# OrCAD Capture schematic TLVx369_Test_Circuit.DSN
size A; title: TLVx369 Cost-Optimized, 800-nA, 1.8-V, Rail-to-Rail I/O; rev: 1.1; note: Datasheet: SBOS757 EVM: N/A
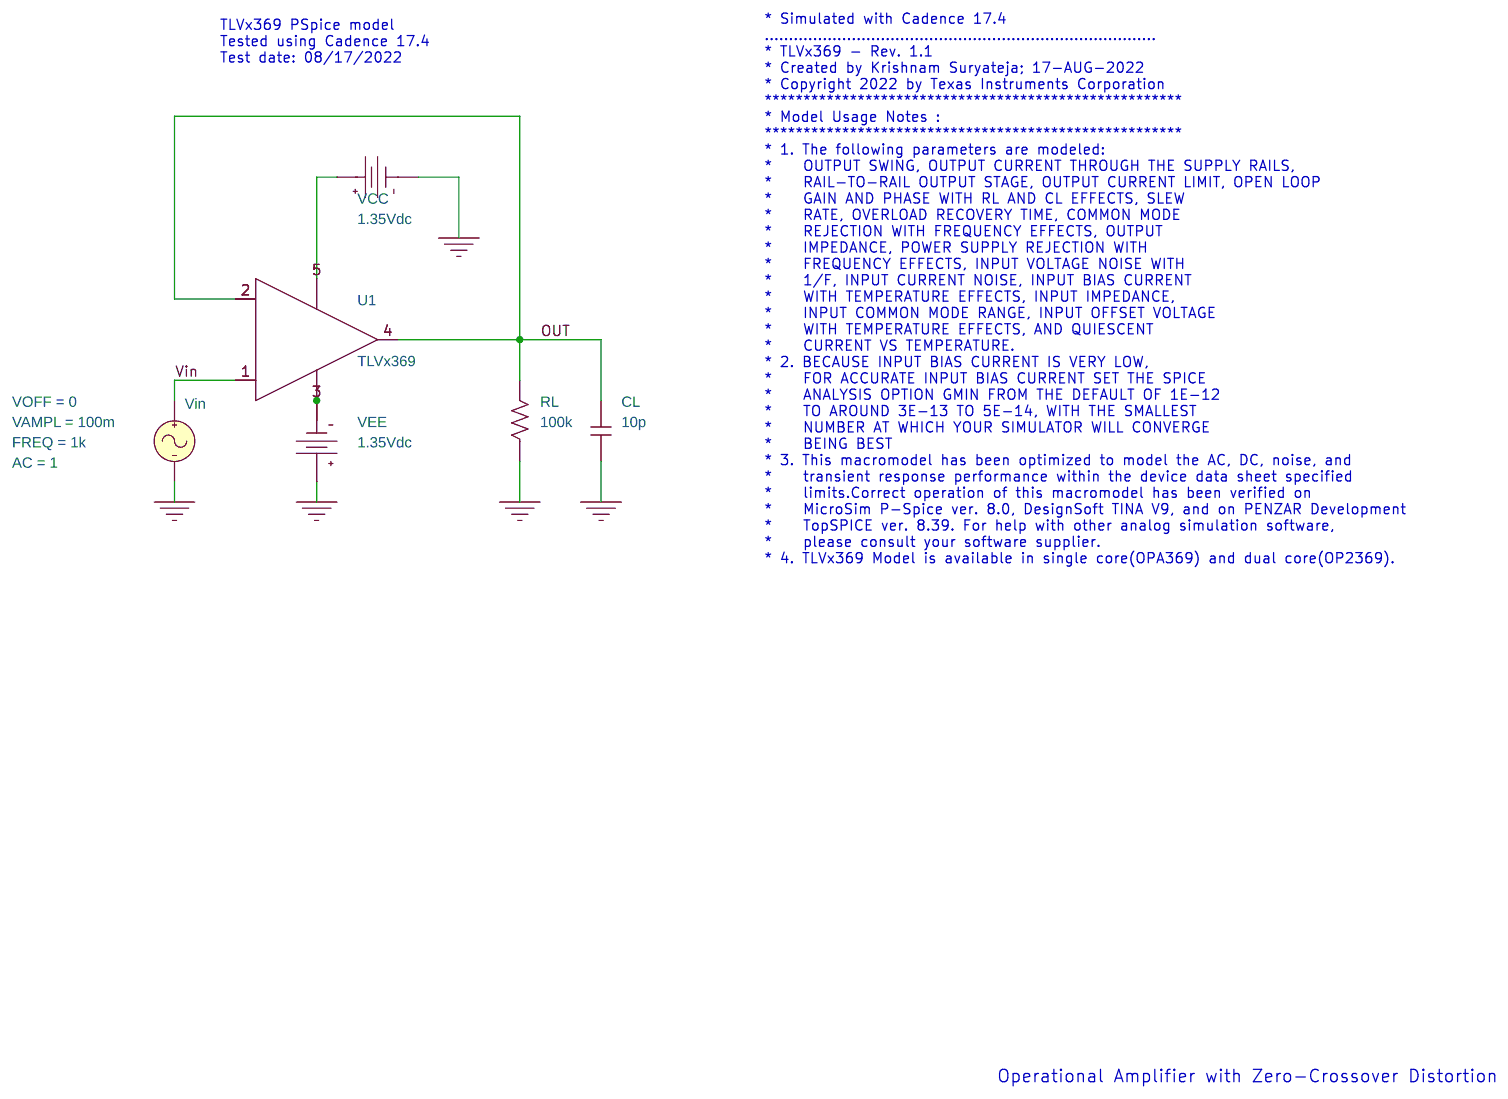
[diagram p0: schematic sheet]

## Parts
CL  10p  [RAD/CK05]
RL  100k  [AX/RC05]
U1  TLVx369
VCC  VDC
VEE  VDC
Vin  VSIN

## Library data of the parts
CL = C
RL = R
U1 = TLVx369
VCC VEE = VDC: DC: 1.35Vdc
Vin = VSIN: AC: 1; FREQ: 1k; VAMPL: 100m; VOFF: 0

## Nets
Vin: U1.1(+) Vin.1(+)
0: CL.1 RL.1 VCC.1(-) VEE.0(+) Vin.2(-)
OUT: CL.2 RL.2 U1.2(-) U1.4(OUT)
N22995: U1.5(V+) VCC.0(+)
N23017: U1.3(V-) VEE.1(-)

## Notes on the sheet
- TLVx369 PSpice model
  Tested using Cadence 17.4
  Test date: 08/17/2022
- * Simulated with Cadence 17.4
  .................................................................................
  * TLVx369 - Rev. 1.1
  * Created by Krishnam Suryateja; 17-AUG-2022
  * Copyright 2022 by Texas Instruments Corporation
  ******************************************************
  * Model Usage Notes :
  ******************************************************
  * 1. The following parameters are modeled:
  *    OUTPUT SWING, OUTPUT CURRENT THROUGH THE SUPPLY RAILS,
  *    RAIL-TO-RAIL OUTPUT STAGE, OUTPUT CURRENT LIMIT, OPEN LOOP
  *    GAIN AND PHASE WITH RL AND CL EFFECTS, SLEW
  *    RATE, OVERLOAD RECOVERY TIME, COMMON MODE
  *    REJECTION WITH FREQUENCY EFFECTS, OUTPUT
  *    IMPEDANCE, POWER SUPPLY REJECTION WITH
  *    FREQUENCY EFFECTS, INPUT VOLTAGE NOISE WITH
  *    1/F, INPUT CURRENT NOISE, INPUT BIAS CURRENT
  *    WITH TEMPERATURE EFFECTS, INPUT IMPEDANCE,
  *    INPUT COMMON MODE RANGE, INPUT OFFSET VOLTAGE
  *    WITH TEMPERATURE EFFECTS, AND QUIESCENT
  *    CURRENT VS TEMPERATURE.
  * 2. BECAUSE INPUT BIAS CURRENT IS VERY LOW,
  *    FOR ACCURATE INPUT BIAS CURRENT SET THE SPICE
  *    ANALYSIS OPTION GMIN FROM THE DEFAULT OF 1E-12
  *    TO AROUND 3E-13 TO 5E-14, WITH THE SMALLEST
  *    NUMBER AT WHICH YOUR SIMULATOR WILL CONVERGE
  *    BEING BEST
  * 3. This macromodel has been optimized to model the AC, DC, noise, and
  *    transient response performance within the device data sheet specified
  *    limits.Correct operation of this macromodel has been verified on
  *    MicroSim P-Spice ver. 8.0, DesignSoft TINA V9, and on PENZAR Development
  *    TopSPICE ver. 8.39. For help with other analog simulation software,
  *    please consult your software supplier.
  * 4. TLVx369 Model is available in single core(OPA369) and dual core(OP2369).
- Operational Amplifier with Zero-Crossover Distortion
